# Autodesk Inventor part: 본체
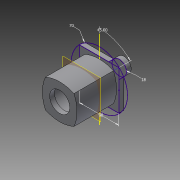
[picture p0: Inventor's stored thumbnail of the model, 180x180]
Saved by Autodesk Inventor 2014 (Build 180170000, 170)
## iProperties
Created: 2016-05
Part Number: 본체
Material: 일반
Document SubType Name: Modeling
Designer: S. S. MOON
Density: 1 g/cm^3
Appearance: 기본값
Author: S. S. MOON
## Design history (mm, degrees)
sketch "스케치1" dims "d0" = 100
  geometry: L1 (35.355, 35.355)-(-35.355, 35.355); L2 (-35.355, 35.355)-(-35.355, -35.355); L3 (-35.355, -35.355)-(35.355, -35.355); L4 (35.355, -35.355)-(35.355, 35.355); A1 r 85.579 centre (0, -42.579) between (35.355, 35.355) and (-35.355, 35.355); A2 r 85.579 centre (-42.579, 0) between (35.355, -35.355) and (35.355, 35.355); A3 r 85.579 centre (0, 42.579) between (-35.355, -35.355) and (35.355, -35.355); A4 r 85.579 centre (42.579, 0) between (-35.355, 35.355) and (-35.355, -35.355); 4 further points
  constraints: 8 end point, 8 point on circle, 4 centre point, 3 equal radius, 2 midpoint, 2 parallel, 1 coincident, 1 horizontal, 1 horizontal alignment, 1 perpendicular, 1 vertical alignment, 3 other
  dimensions: "d3" = 86 dimension on A3 A1; "d4" = 86 dimension on A4 A2
extrude "돌출1" new body sketch "스케치1" stored distance "d5" = 98; taper "d6" = 0 deg
sketch "스케치2" dims "d11" = 70
  geometry: L1 (49, -49)-(-49, -49); L2 (-49, -49)-(-49, 49); L3 (-49, 49)-(49, 49); L4 (49, 49)-(49, -49); L5 (0, 0)-(49.497, -49.497); L6 (0, 98)-(0, -98) reference; L7 (62.225, -36.77)-(49, -23.544); L8 (36.77, -62.225)-(23.544, -49); A1 r 18 centre (49.497, -49.497) between (62.225, -36.77) and (36.77, -62.225); 3 further points
  constraints: 14 end point, 5 parallel, 2 coincident, 2 midpoint, 2 point on circle, 2 point on line, 2 tangent, 1 centre point, 1 horizontal, 1 horizontal alignment, 1 perpendicular, 1 vertical alignment, 3 other
  dimensions: "d7" = 98 distance of L2.end L3.end; "d9" = 45 deg angle of L6 L5; "d12" = 18 radius of A1
extrude "돌출2" join sketch "스케치2" distance "d13" = 12; taper "d14" = 0 deg
extrude "돌출3" join sketch "스케치2" distance "d15" = 12; taper "d16" = 0 deg
node "작업 평면1"
sketch "스케치4"
  geometry: 1 further point
hole "구멍1" sketch "스케치4" diameter "d18" = 50; stored, may be unused: countersink angle "d22" = 90 deg, drill point angle "d24" = 118 deg; dims "d19" = 6, "d20" = 70, "d21" = 43, "d23" = 8
hole "구멍2" sketch "스케치4" diameter "d25" = 50; stored, may be unused: countersink angle "d29" = 90 deg, drill point angle "d31" = 118 deg; dims "d26" = 6, "d27" = 70, "d28" = 43, "d30" = 8
node "솔리드1"
other parameters: "d17" = -55
